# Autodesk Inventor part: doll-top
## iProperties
Author: Administrator
Created: 2001-10
Part Number: doll-top
Document SubType Name: Modeling
Designer: Administrator
Control State: 0
Master: False
Checked Out: False
PropertySet Name: Design Tracking Control
Shininess: 64.0
Angle Display Precision: 2
Document Length Units: 11272
Document Angle Units: 11286
Document Time Units: 11279
Document Mass Units: 11290
Document Length Units Precision: 3
Document Angle Units Precision: 2
Compacted: True
PropertySet Name: _Private Model Information
Density: 0.0
Volumn: 0.0
Area: 0.0
PropertySet Name: Model Information
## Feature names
1. Revolution1
2. Shell1
3. Split1
4. Extrusion1
